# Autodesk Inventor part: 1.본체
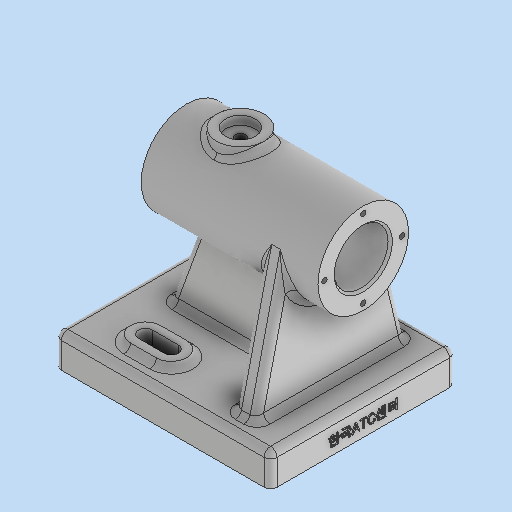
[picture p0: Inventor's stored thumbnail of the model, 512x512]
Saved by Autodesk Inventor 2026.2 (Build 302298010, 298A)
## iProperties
Created: 2026-09
Part Number: 1.본체
Material: 일반
Document SubType Name: Modeling
Designer: PC-2-06
Density: 1 g/cm^3
Appearance: 기본값
Author: PC-2-06
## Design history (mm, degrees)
sketch "스케치1"
  geometry: L1 (-100, 43)-(0, 43); L2 (0, 43)-(0, -43); L3 (0, -43)-(-100, -43); L4 (-100, -43)-(-100, 43); 1 further point
  constraints: 8 end point, 2 parallel, 1 horizontal, 1 midpoint, 1 perpendicular
  dimensions: "d0" = 86 distance between parallel lines of L3 L1; "d1" = 100 distance between parallel lines of L2 L4; "d2" = 43 distance from line of point (0, 0) L1 (= 0.5 x d0)
extrude "돌출1" new body sketch "스케치1" distance "d3" = 15; taper "d4" = 0 deg
sketch "스케치2"
  geometry: L1 (0, 0)-(0, 86) reference; C1 r 21 at (-72, 43); 2 further points
  constraints: 1 centre point, 1 horizontal alignment, 1 midpoint
  dimensions: "d5" = 42 diameter of C1; "d9" = 72 distance from line of C1.centre L1
extrude "돌출2" join sketch "스케치2" distance "d6" = 82; taper "d7" = 0 deg
node "작업 평면1"
sketch "스케치3"
  geometry: L1 (82, -21)-(82, 21) reference; C1 r 11 at (57, 0); 1 further point
  constraints: 1 centre point, 1 horizontal alignment
  dimensions: "d10" = 25 distance from line of C1.centre L1; "d11" = 22 diameter of C1
extrude "돌출3" join sketch "스케치3" stored distance "d12" = 82; taper "d13" = 0 deg
node "작업 평면2"
sketch "스케치4"
  geometry: L1 (-15, 0)-(-15, 86) reference; L2 (-76.814, 22.559)-(-15, 8); L3 (-76.814, 63.441)-(-15, 78); L4 (0, 0)-(-15, 0) reference; L5 (0, 86)-(-15, 86) reference; A1 r 21 centre (-72, 43) between (-76.814, 22.559) and (-76.814, 63.441) reference; 2 further points
  constraints: 4 end point, 2 point on circle, 2 point on line, 2 tangent, 1 midpoint
  dimensions: "d15" = 8 distance from line of L2.end L4; "d16" = 8 vertical distance of point (-7.5, 86) L3.end
extrude "돌출4" join sketch "스케치4" distance "d17" = 10; taper "d18" = 0 deg
sketch "스케치5"
  geometry: L1 (70.133, 55.846)-(85, 15); L2 (100, 15)-(0, 15) reference; L3 (100, 0)-(100, 15) reference; 1 further point
  constraints: 2 end point, 1 point on line
  dimensions: "d19" = 15 distance from line of L1.end L3; "d20" = 70 deg angle of L2 L1
feature "리브1" sketch "스케치5" dims "d21" = 1, "d22" = 10, "d23" = 0, "d24" = 0, "d25" = 1, "d26" = 1
sketch "스케치6"
  geometry: L1 (-74, 27)-(-62, 27); L2 (-74, 20)-(-62, 20); L3 (-62, 34)-(-74, 34); L4 (-100, 43)-(-100, -43) reference; A1 r 7 centre (-74, 27) between (-74, 34) and (-74, 20); A2 r 7 centre (-62, 27) between (-62, 20) and (-62, 34); 2 further points
  constraints: 8 end point, 4 point on circle, 4 tangent, 2 centre point, 1 horizontal, 1 midpoint, 1 parallel
  dimensions: "d27" = 27 vertical distance of L1.end point (0, 0); "d28" = 26 distance from line of L1.start L4; "d29" = 12 distance of L1.end L1.start; "d30" = 7 radius of A2
extrude "돌출5" join sketch "스케치6" distance "d31" = 3; taper "d32" = 0 deg
sketch "스케치7"
  geometry: L1 (-62, 34)-(-74, 34) reference; L2 (-62, 34)-(-74, 34) reference; L3 (-74, 20)-(-62, 20) reference; L4 (-74, 30.3)-(-62, 30.3); L5 (-62, 23.7)-(-74, 23.7); A1 r 7 centre (-62, 27) between (-62, 20) and (-62, 34) reference; A2 r 7 centre (-74, 27) between (-74, 34) and (-74, 20) reference; A3 r 3.3 centre (-74, 27) between (-74, 30.3) and (-74, 23.7); A4 r 3.3 centre (-62, 27) between (-62, 23.7) and (-62, 30.3); 1 further point
  constraints: 4 end point, 4 point on circle, 2 centre point, 3 other
  dimensions: "d33" = 6.6 distance between parallel lines of L5 L4
extrude "돌출6" cut sketch "스케치7" extent not by distance; stored distance "d34" = 0; taper "d35" = 0 deg
sketch "스케치8"
  geometry: C1 r 21 at (0, 0) reference; 2 further points
  constraints: 1 coincident
hole "구멍1" sketch "스케치8" at (0, 0) diameter "d36" = 25; stored, may be unused: countersink angle "d40" = 90 deg, drill point angle "d42" = 118 deg; dims "d37" = 8, "d38" = 29, "d39" = 62, "d41" = 10
sketch "스케치9"
  geometry: C1 r 11 at (0, 0) reference; 2 further points
  constraints: 1 coincident
hole "구멍2" sketch "스케치9" at (0, 0) diameter "d43" = 4.917; stored, may be unused: countersink angle "d47" = 90 deg, drill point angle "d49" = 0 deg; dims "d44" = 12, "d45" = 14, "d46" = 4, "d48" = 8
sketch "스케치10" dims "d50" = 36
  geometry: C1 r 21 at (0, 0) reference; 3 further points
  constraints: 2 horizontal alignment, 1 coincident, 2 other
hole "구멍3" sketch "스케치10" at (18, 0) diameter "d51" = 2.459; stored, may be unused: countersink angle "d55" = 90 deg, drill point angle "d57" = 118 deg; dims "d52" = 8, "d53" = 14, "d54" = 4, "d56" = 10
sketch "스케치11" dims "d61" = 36
  geometry: C1 r 12.5 at (0, 0) reference; 3 further points
  constraints: 2 horizontal alignment, 3 other
hole "구멍4" sketch "스케치11" at (-18, 0) diameter "d62" = 2.459; stored, may be unused: countersink angle "d66" = 90 deg, drill point angle "d68" = 118 deg; dims "d63" = 8, "d64" = 4, "d65" = 2, "d67" = 10
fillet "모깎기1" dims "d72" = 3
fillet "모깎기2" dims "d73" = 3
fillet "모깎기3" dims "d74" = 3
fillet "모깎기4" dims "d75" = 3
chamfer "모따기1" distance "d76" = 1; stored, may be unused: second distance "d77" = 2, angle "d78" = 45 deg
sketch "스케치12"
  geometry: L1 (-8.402, 23.408)-(-8.402, 56.592); L2 (-8.402, 56.592)-(-3.598, 56.592); L3 (-3.598, 56.592)-(-3.598, 23.408); L4 (-3.598, 23.408)-(-8.402, 23.408); L5 (-6, 23.408)-(-6, 56.592); L6 (-3.598, 40)-(-8.402, 40); L7 (0, 0)-(0, 80) reference; 2 further points
  constraints: 5 midpoint, 4 end point, 1 point on line, 2 other
  dimensions: "d79" = 6 distance between parallel lines of L7 L5
feature "엠보싱1" sketch "스케치12" dims "d0" = 86, "d1" = 100, "d2" = 43 (= 0.5 x d0), "d80" = 0.5, "d81" = 0
node "솔리드1"
mirror "미러1"
pattern_circular "원형 패턴1" dims angle "d59" = 360 deg
pattern_circular "원형 패턴2" dims angle "d70" = 360 deg
node "투영된 루프1"
feature "A9D066F2-1C7D-4E18-AEED-F7BC21143FA4" dims "d36" = 25, "d37" = 8, "d38" = 29, "d39" = 62, "d40" = 90 deg, "d41" = 10, "d42" = 118 deg
other parameters: "d8" = -96, "d14" = -15
